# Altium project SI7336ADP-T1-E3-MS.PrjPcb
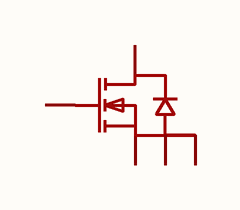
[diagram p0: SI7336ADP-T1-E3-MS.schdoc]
1 sheet, 1 parts. Net scope: global (net labels, ports and power ports of the same name join across sheets).

## Sheet SI7336ADP-T1-E3-MS.schdoc
size 127 x 101 mm

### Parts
Q?  si7336adp-t1-e3-ms  [TDSON-8_L5.9-W5.2-P1.27-BL-1]  (value not drawn)

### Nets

Not connected (* = marked no-connect by the designer): Q? 1(S) 2(S) 3(S) 4(G) 5(D)

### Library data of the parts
Q? = si7336adp-t1-e3-ms: 数量:1个N沟道;漏源电压(Vdss):30V;连续漏极电流(Id):150A;导通电阻(RDS(on)):2mΩ@10V;耗散功率(Pd):187W;阈值电压(Vgs(th)):1.2V;; Manufacturer: MSKSEMI(美森科); AddInBom: yes; ModelId: 6d3ef2b64d5a4f2dbd2ee02e0c7053d2; ModelTransform: 205.511,242.1255,0,0,0,0,0,42.913,0; Number: 1个N沟道; Drain to Source Voltage: 30V; Current - Continuous Drain(Id): 150A; Pd - Power Dissipation: 187W; Gate Threshold Voltage (Vgs(th)): 1.2V; Gate Charge(Qg): 56.9nC; Input Capacitance(Ciss): 4.345nF; Reverse Transfer Capacitance (Crss@Vds): 225pF; Configuration: 独立式; Type: N沟道; Output Capacitance(Coss): 340pF; Vgs: ±20V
